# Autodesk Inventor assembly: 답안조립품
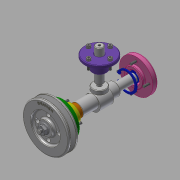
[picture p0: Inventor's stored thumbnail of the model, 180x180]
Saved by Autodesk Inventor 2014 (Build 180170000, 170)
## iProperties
Created: 2020-08
Part Number: 답안조립품
Document SubType Name: Assembly
Designer: kh
Author: kh
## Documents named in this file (18)
- C:\Users\kh\Desktop\700806V1024\답안조립품.iam
- C:\Users\kh\Desktop\700806V1024\본체.ipt
- C:\Users\kh\Desktop\700806V1024\V-벨트풀리.ipt
- C:\Users\kh\Desktop\700806V1024\너트 M8.ipt
- C:\Users\kh\Desktop\700806V1024\뒤커버.ipt
- C:\Users\kh\Desktop\700806V1024\멈춤링 15x1.ipt
- C:\Users\kh\Desktop\700806V1024\멈춤링 35x1.6.ipt
- 멈춤링 35x1.6.ipt
- C:\Users\kh\Desktop\700806V1024\베어링 6202.ipt
- 베어링 6202.ipt
- C:\Users\kh\Desktop\700806V1024\볼트 M4.ipt
- C:\Users\kh\Desktop\700806V1024\상부커버.ipt
- C:\Users\kh\Desktop\700806V1024\슬라이드.ipt
- C:\Users\kh\Desktop\700806V1024\앞커버.ipt
- C:\Users\kh\Desktop\700806V1024\오일 실 15 30 7.ipt
- C:\Users\kh\Desktop\700806V1024\칼라.ipt
- C:\Users\kh\Desktop\700806V1024\키 3x3x12.ipt
- C:\Users\kh\Desktop\700806V1024\편심축.ipt
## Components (1 placed, 1 different names)
1. V-벨트풀리:1 — Insert:12, Mate:12, Insert:13
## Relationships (3: Insert 2, Mate 1)
- Insert:12: V-벨트풀리:1
- Mate:12: V-벨트풀리:1
- Insert:13: V-벨트풀리:1
